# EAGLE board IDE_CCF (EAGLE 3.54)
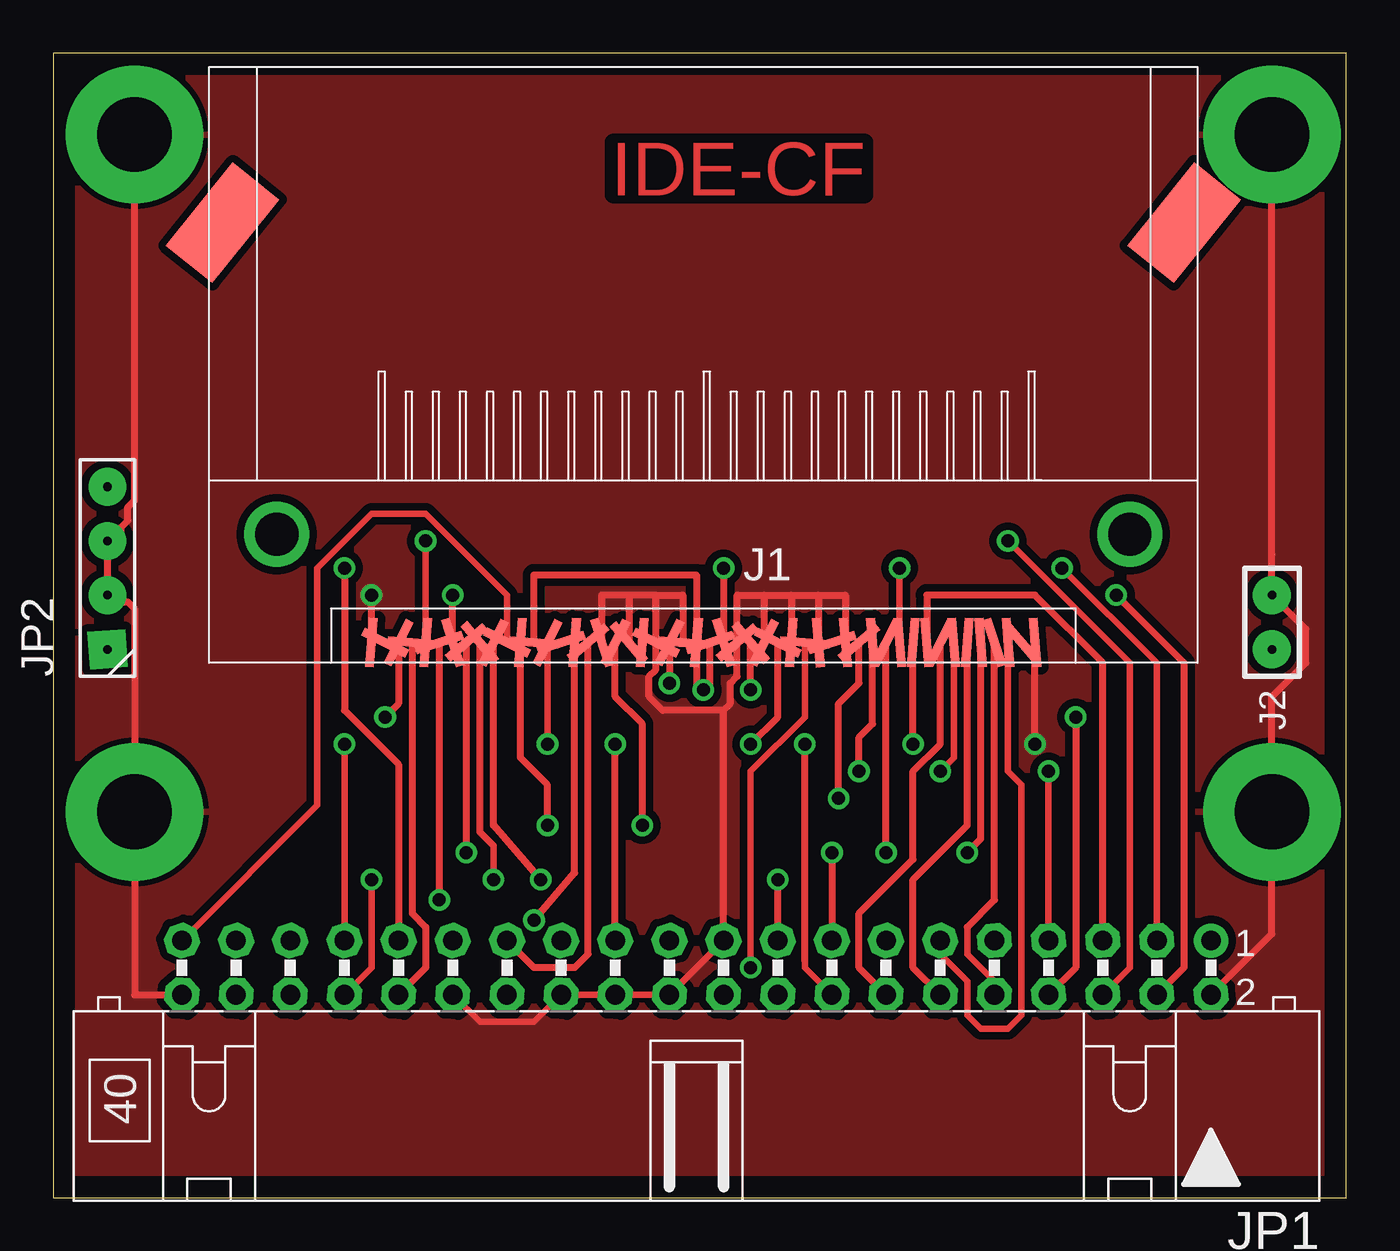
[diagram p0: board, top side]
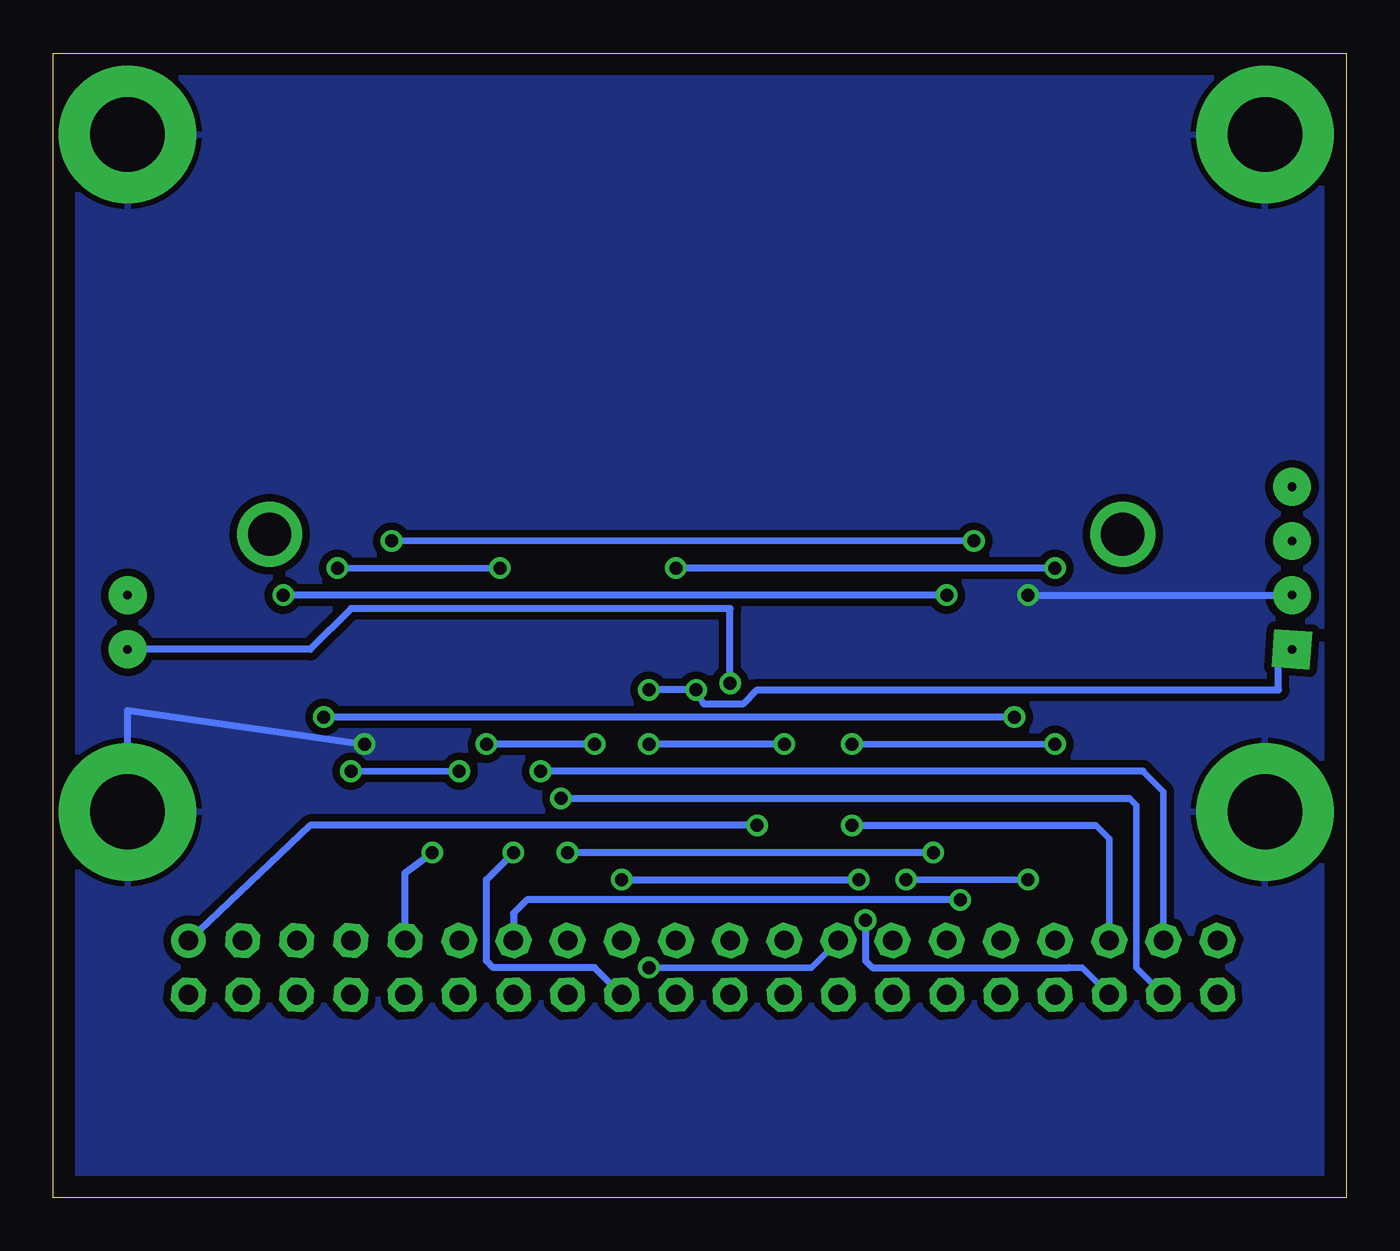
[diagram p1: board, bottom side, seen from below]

Size 60.63 x 53.64 mm. Coordinates in mm from the lower left corner, seen from the top.
Outline: 0,53.64 0,0 60.63,0 60.63,53.64 0,53.64
Copper layers used: Top, Bottom

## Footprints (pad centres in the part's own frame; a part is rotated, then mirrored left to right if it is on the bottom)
SMT = drill 2.032 pad 3.048 round: @1 -20.003,-5.08; @2 20.003,-5.08 | smd 2.794 x 5.004 rotated 321.2: @3 -22.543,-19.685; @4 22.543,-19.685 | smd 0.406 x 2.311 rotated 4.3:  -15.557,0;  -4.128,0 | smd 0.406 x 2.311 rotated 4.4:  -14.287,0;  8.572,0 | smd 0.406 x 2.311 rotated 4.5:  -13.018,0;  -9.842,0 | smd 0.406 x 2.311 rotated 4.6:  -11.748,0;  2.857,0 | smd 0.406 x 2.311 rotated 4.7:  -10.477,0;  -9.207,0;  15.557,0 | smd 0.406 x 2.311 rotated 4.8:  -7.938,0 | smd 0.406 x 2.311 rotated 4.9:  -6.668,0 | smd 0.406 x 2.311 rotated 5:  -5.397,0 | smd 0.406 x 2.311 rotated 26.8:  -2.857,0 | smd 0.406 x 2.311 rotated 49.3:  -1.587,0 | smd 0.406 x 2.311 rotated 71.8:  -0.318,0 | smd 0.406 x 2.311 rotated 94.3:  0.953,0 | smd 0.406 x 2.311 rotated 116.8:  2.223,0 | smd 0.406 x 2.311 rotated 139.3:  3.493,0 | smd 0.406 x 2.311 rotated 161.8:  4.763,0 | smd 0.406 x 2.311 rotated 184.3:  6.032,0 | smd 0.406 x 2.311 rotated 206.8:  7.303,0 | smd 0.406 x 2.311 rotated 26.9:  9.842,0 | smd 0.406 x 2.311 rotated 49.4:  11.113,0 | smd 0.406 x 2.311 rotated 71.9:  12.383,0 | smd 0.406 x 2.311 rotated 94.4:  13.652,0 | smd 0.406 x 2.311 rotated 116.9:  14.922,0 | smd 0.406 x 2.311 rotated 139.4:  -14.922,0 | smd 0.406 x 2.311 rotated 161.9:  -13.652,0 | smd 0.406 x 2.311 rotated 184.4:  -12.383,0 | smd 0.406 x 2.311 rotated 206.9:  -11.113,0 | smd 0.406 x 2.311 rotated 27:  -8.572,0 | smd 0.406 x 2.311 rotated 49.5:  -7.303,0 | smd 0.406 x 2.311 rotated 72:  -6.032,0 | smd 0.406 x 2.311 rotated 94.5:  -4.763,0 | smd 0.406 x 2.311 rotated 117:  -3.493,0 | smd 0.406 x 2.311 rotated 139.5:  -2.223,0 | smd 0.406 x 2.311 rotated 162:  -0.953,0 | smd 0.406 x 2.311 rotated 184.5:  0.318,0 | smd 0.406 x 2.311 rotated 207:  1.587,0 | smd 0.406 x 2.311 rotated 27.1:  4.128,0 | smd 0.406 x 2.311 rotated 49.6:  5.397,0 | smd 0.406 x 2.311 rotated 72.1:  6.668,0 | smd 0.406 x 2.311 rotated 94.6:  7.938,0 | smd 0.406 x 2.311 rotated 117.1:  9.207,0 | smd 0.406 x 2.311 rotated 139.6:  10.477,0 | smd 0.406 x 2.311 rotated 162.1:  11.748,0 | smd 0.406 x 2.311 rotated 184.6:  13.018,0 | smd 0.406 x 2.311 rotated 207.1:  14.287,0
MPER = drill 0.406 pad 1.778 round:  -1.27,0;  1.27,0
40L = drill 0.914 pad 1.6 round:  -24.13,-1.27 | drill 0.914 pad 1.6 octagon:  -24.13,1.27;  -21.59,-1.27;  -21.59,1.27;  -19.05,-1.27;  -19.05,1.27;  -16.51,-1.27;  -16.51,1.27;  -13.97,-1.27;  -13.97,1.27;  -11.43,-1.27;  -11.43,1.27;  -8.89,-1.27;  -8.89,1.27;  -6.35,-1.27;  -6.35,1.27;  -3.81,-1.27;  -3.81,1.27;  -1.27,-1.27;  -1.27,1.27;  1.27,-1.27;  1.27,1.27;  3.81,-1.27;  3.81,1.27;  6.35,-1.27;  6.35,1.27;  8.89,1.27;  8.89,-1.27;  11.43,1.27;  11.43,-1.27;  13.97,1.27;  13.97,-1.27;  16.51,-1.27;  16.51,1.27;  19.05,-1.27;  19.05,1.27;  21.59,1.27;  21.59,-1.27;  24.13,-1.27;  24.13,1.27
4 = drill 0.406 pad 1.778 square:  0,0 | drill 0.406 pad 1.778 round:  5.08,0;  7.62,0;  2.54,0
HRUNG = drill 3.505 pad 6.452 round:  0,0

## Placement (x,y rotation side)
J1  CFLASH1  [SMT]  30.48,26.02 180 top
J2  JUMPER  [MPER]  57.15,26.97 270 top
JP1  PINHD-2X20  [40L]  30.16,10.77 180 top
JP2  PINHD-1X4  [4]  2.54,25.7 90 top
U$13  BOHRUNG  [HRUNG]  3.81,49.83 270 top
U$14  BOHRUNG  [HRUNG]  57.15,49.83 270 top
U$16  BOHRUNG  [HRUNG]  57.15,18.08 270 top
U$17  BOHRUNG  [HRUNG]  3.81,18.08 270 top

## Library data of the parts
J1 = ic_holg
J2 JP2 = holg_plt
JP1 = CON-ML
U$13 U$14 U$16 U$17 = holgnorm

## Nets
+5V: J1. JP2.
/CE1: J1. JP1.
/CE2: J1. JP1.
/DASP: J1. JP1.
/IOCS16: J1. JP1.
/IORD: J1. JP1.
/IOWR: J1. JP1.
/RESET: J1. JP1.
GND: J1. J2. JP1. JP2. U$13. U$14. U$16. U$17.
HA0: J1. JP1.
HA1: J1. JP1.
HA2: J1. JP1.
HD0: J1. JP1.
HD1: J1. JP1.
HD2: J1. JP1.
HD3: J1. JP1.
HD4: J1. JP1.
HD5: J1. JP1.
HD6: J1. JP1.
HD7: J1. JP1.
HD8: J1. JP1.
HD9: J1. JP1.
HD10: J1. JP1.
HD11: J1. JP1.
HD12: J1. JP1.
HD13: J1. JP1.
HD14: J1. JP1.
HD15: J1. JP1.
IORDY: J1. JP1.
IRQ: J1. JP1.
MAS/SLA: J1. J2.
PDIAG: J1. JP1.

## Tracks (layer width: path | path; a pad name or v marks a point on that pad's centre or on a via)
+5V  (via drill 0.61 pad 1.02)
  Top 0.317: 22.54,26.02 22.54,29.19 30.16,29.19 30.16,26.02 30.16,23.79 v30.48,23.79 30.8,23.79 30.8,26.02 | v32.7,23.79 32.7,26.02
  Bottom 0.317: v32.7,23.79 v30.48,23.79 30.16,23.16 28.26,23.16 27.62,23.79 3.18,23.79 3.18,25.06 2.54,25.7
/CE1  (via drill 0.61 pad 1.02)
  Top 0.317: v37.78,19.98 37.78,21.57 38.42,22.2 38.42,26.02
  Bottom 0.305: 8.57,12.04 8.57,19.03 9.52,19.98
  Bottom 0.317: 9.52,19.98 v37.78,19.98
/CE2  (via drill 0.61 pad 1.02)
  Top 0.317: v36.83,18.71 36.83,23.16 37.78,24.11 37.78,26.02
  Bottom 0.305: 8.57,9.5 9.84,10.77 9.84,18.39 10.16,18.71
  Bottom 0.317: v36.83,18.71 10.16,18.71
/DASP
  Top 0.305: 6.03,12.04 12.38,18.39 12.38,29.51 14.92,32.05 17.46,32.05 21.27,28.24 21.27,26.02
/IOCS16
  Top 0.317: 16.83,26.02 16.83,13.31 17.46,12.68 17.46,10.77 16.19,9.5
/IORD  (via drill 0.61 pad 1.02)
  Top 0.305: 35.24,26.02 35.24,22.52 32.7,19.98 v32.7,10.77
  Bottom 0.305: v32.7,10.77 25.08,10.77 23.81,12.04
/IOWR  (via drill 0.61 pad 1.02)
  Top 0.317: 33.97,26.02 33.97,22.52 v32.7,21.25 | 26.35,12.04 v26.35,21.25
  Bottom 0.317: v26.35,21.25 v32.7,21.25
/RESET  (via drill 0.61 pad 1.02)
  Top 0.317: v27.62,17.44 27.62,22.2 26.35,23.48 26.35,26.02
  Bottom 0.317: v27.62,17.44 48.58,17.44 54.29,12.04
GND  (via drill 0.61 pad 1.02)
  Top 0.305: 28.89,9.5 26.35,9.5 23.81,9.5 22.54,8.23 20,8.23 18.73,9.5
  Top 0.317: 57.15,28.24 U$14. | v46.04,21.25 46.04,26.02 | 54.29,9.5 57.15,12.36 U$16. 57.15,23.48 58.74,25.06 58.74,26.65 57.15,28.24 | 57.15,28.24 57.15,30.14 | 26.99,28.24 25.72,28.24 25.72,26.02 | 26.99,28.24 26.99,26.02 | 28.26,28.24 26.99,28.24 | 28.26,28.24 28.26,26.02 28.26,24.74 27.94,24.43 27.94,23.48 28.57,22.84 31.43,22.84 | 28.26,28.24 29.53,28.24 29.53,26.02 | 33.34,28.24 32.07,28.24 32.07,26.02 32.07,24.43 31.75,24.11 31.75,23.16 31.43,22.84 | 33.34,28.24 33.34,26.02 | 33.34,28.24 34.61,28.24 | 34.61,28.24 34.61,26.02 | 34.61,28.24 35.88,28.24 | 35.88,28.24 35.88,26.02 | 35.88,28.24 37.15,28.24 37.15,26.02 | 28.89,9.5 31.43,12.04 31.43,22.84 | JP1. 3.81,9.5 U$17. 3.81,27.6 3.49,27.92 3.18,27.92 JP2. 2.54,30.78 3.18,31.09 3.18,31.41 3.49,31.73 3.49,32.37 3.81,32.68 U$13. | J1. v14.92,28.24
  Bottom 0.317: U$16. 57.15,22.84 v46.04,21.25 | v14.92,28.24 JP2.
  pour Top (isolate 0.356): 60.33,0.3 60.33,53.32 0.32,53.32 0.32,0.3
  pour Bottom (isolate 0.356): 60.33,0.3 60.33,53.32 0.32,53.32 0.32,0.3
HA0  (via drill 0.61 pad 1.02)
  Top 0.317: 21.91,26.02 21.91,20.62 23.18,19.35 v23.18,17.44
  Bottom 0.305: 11.11,12.04 11.11,16.81 11.75,17.44
  Bottom 0.317: v23.18,17.44 11.75,17.44
HA1  (via drill 0.61 pad 1.02)
  Top 0.305: v23.18,21.25 23.18,26.02 | v13.65,21.25 13.65,12.04
  Bottom 0.305: v23.18,21.25 v13.65,21.25
HA2  (via drill 0.61 pad 1.02)
  Top 0.317: v22.54,13 24.45,15.22 24.45,26.02
  Bottom 0.305: 11.11,9.5 12.38,10.77 13.02,10.77
  Bottom 0.317: v22.54,13 22.54,11.09 22.23,10.77 13.02,10.77
HD0  (via drill 0.61 pad 1.02)
  Top 0.317: v22.86,14.9 20.64,17.44 20.64,26.02 | 33.97,12.04 v33.97,14.9
  Bottom 0.317: v33.97,14.9 v22.86,14.9
HD1  (via drill 0.61 pad 1.02)
  Top 0.317: 19.37,26.02 v19.37,16.17 | v36.51,16.17 36.51,12.04
  Bottom 0.317: v19.37,16.17 v36.51,16.17
HD2  (via drill 0.61 pad 1.02)
  Top 0.317: 18.1,26.02 v18.1,13.95
  Bottom 0.317: v18.1,13.95 38.42,13.95 39.05,13.31 39.05,12.04
HD3
  Top 0.305: 44.77,26.02 44.77,19.98 45.4,19.35 45.4,8.55 44.77,7.92 43.5,7.92 42.86,8.55 42.86,10.14 41.59,11.41 41.59,12.04
HD4  (via drill 0.61 pad 1.02)
  Top 0.317: v42.86,16.17 43.5,16.81 43.5,26.02
  Bottom 0.317: v42.86,16.17 44.13,15.22 44.13,12.04
HD5  (via drill 0.61 pad 1.02)
  Top 0.305: 42.23,26.02 42.23,20.62 v41.59,19.98 | 46.67,12.04 v46.67,19.98
  Bottom 0.305: v46.67,19.98 v41.59,19.98
HD6
  Top 0.317: 40.96,26.02 40.96,28.24 46.04,28.24 49.21,25.06 49.21,12.04
HD7  (via drill 0.61 pad 1.02)
  Top 0.305: v39.69,29.51 39.69,26.02 | v47.31,29.51 51.75,25.06 51.75,12.04
  Bottom 0.305: v47.31,29.51 v39.69,29.51
HD8  (via drill 0.61 pad 1.02)
  Top 0.317: v49.85,28.24 53.02,25.06 53.02,10.77 51.75,9.5 | 18.73,26.02 v18.73,28.24
  Bottom 0.317: v18.73,28.24 v49.85,28.24
HD9  (via drill 0.61 pad 1.02)
  Top 0.305: 49.21,9.5 50.48,10.77 50.48,25.06 v44.77,30.78 | 17.46,26.02 v17.46,30.78
  Bottom 0.305: v17.46,30.78 v44.77,30.78
HD10  (via drill 0.61 pad 1.02)
  Top 0.317: v47.94,22.52 47.94,10.77 46.67,9.5 | 16.19,26.02 16.19,23.16 v15.56,22.52
  Bottom 0.317: v15.56,22.52 v47.94,22.52
HD11
  Top 0.305: 42.86,12.68 42.86,11.41 44.13,10.14 44.13,9.5
  Top 0.317: 42.86,12.68 44.13,13.95 44.13,26.02
HD12
  Top 0.317: 42.86,26.02 42.86,17.44 40.32,14.9 40.32,10.77 41.59,9.5
HD13
  Top 0.317: 41.59,26.02 41.59,21.25 40.32,19.98 40.32,15.86 37.78,13.31 37.78,10.77 39.05,9.5
HD14  (via drill 0.61 pad 1.02)
  Top 0.305: 35.24,11.09 35.24,10.77 36.51,9.5
  Top 0.317: 35.24,11.09 v35.24,21.25 | v40.32,21.25 40.32,26.02
  Bottom 0.317: v35.24,21.25 v40.32,21.25
HD15  (via drill 0.61 pad 1.02)
  Top 0.317: v39.05,16.17 39.05,26.02
  Bottom 0.317: v39.05,16.17 40.32,14.9 40.32,11.09 40.01,10.77 35.24,10.77 33.97,9.5
IORDY
  Top 0.317: 25.08,26.02 25.08,11.41 24.45,10.77 22.54,10.77 21.27,12.04
IRQ  (via drill 0.61 pad 1.02)
  Top 0.317: v13.65,29.51 13.65,22.84 16.19,20.3 16.19,12.04 | v31.43,29.51 31.43,26.02
  Bottom 0.317: v13.65,29.51 v31.43,29.51
MAS/SLA  (via drill 0.61 pad 1.02)
  Top 0.317: 28.89,26.02 v28.89,24.11
  Bottom 0.317: v28.89,24.11 28.89,27.6 46.67,27.6 48.58,25.7 J2.
PDIAG  (via drill 0.61 pad 1.02)
  Top 0.305: 20.64,16.49 v20.64,14.9 | v14.92,14.9 14.92,10.77 13.65,9.5
  Top 0.317: 20.64,16.49 20,17.12 20,26.02
  Bottom 0.305: v20.64,14.9 v14.92,14.9

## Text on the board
Top: IDE-CF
